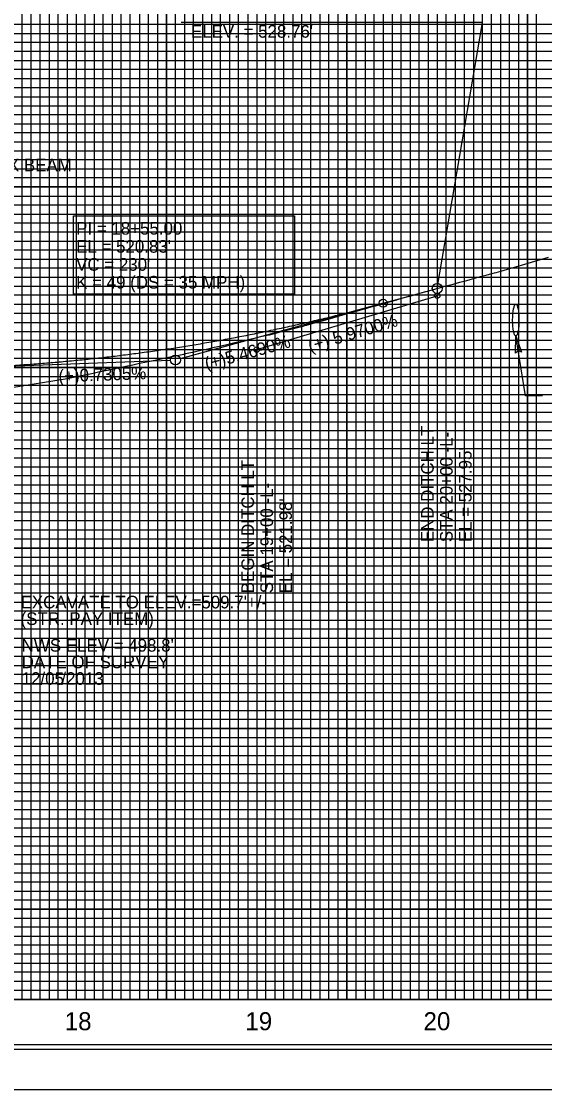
# Model space of a CAD drawing. Extents: x 572694 to 574378, y -52955 to -51855.
# Drawn here: x 573681 to 573971, y -52955 to -52363 of the extents above; entities that cross this region are included whole.
import ezdxf

# ---------------------------------------------------------------- set-up
doc = ezdxf.new("R2010")
doc.units = 0
for name, color, linetype in [('Exist Profile Cell', 7, 'Continuous'), ('Exist Vertical Profile Ground Line', 7, 'Continuous'), ('Exist Vertical Profile Horizontal Axis Label Major', 7, 'Continuous'), ('Prop Drainage Structure Box Reinforced Concrete', 7, 'Continuous'), ('Prop Drainage Structure Box Reinforced Concrete Label', 7, 'Continuous'), ('Prop Grid Mask', 7, 'Continuous'), ('Prop PFL Text', 7, 'Continuous'), ('Prop Vertical Profile Curve Label', 7, 'Continuous'), ('Prop Vertical Profile Ditch Grade Left', 7, 'Continuous'), ('Prop Vertical Profile Ditch Grade Left Label', 7, 'Continuous'), ('Prop Vertical Profile Grade', 7, 'Continuous'), ('Prop Vertical Profile Grade Label', 7, 'Continuous'), ('Prop VPI Ditch Grade Left Label', 7, 'Continuous'), ('Sheet Cutting Line CELL', 7, 'Continuous'), ('Sheet DOT Grid CELL', 7, 'Continuous'), ('Sheet Plot Border Inside CELL', 7, 'Continuous'), ('Sheet Plot Border Outside CELL', 7, 'Continuous'), ('Sheet Profile CELL', 7, 'Continuous'), ('Sheet Profile Grid Major CELL', 7, 'Continuous'), ('Sheet Profile Grid Middle CELL', 7, 'Continuous'), ('Sheet Profile Grid Minor CELL', 7, 'Continuous'), ('Typical Terminator CELL', 7, 'Continuous')]:
    doc.layers.add(name, color=color, linetype=linetype)

msp = doc.modelspace()

# ---------------------------------------------------------------- linework, layer by layer
at = {"layer": 'Exist Profile Cell'}
msp.add_line((572911.5, -52905.14), (574213.46, -52905.14), dxfattribs=at)
at = {"layer": 'Exist Vertical Profile Ground Line'}
for points in [[(573765.48, -52548.86), (573769.25, -52548.07), (573771.11, -52547.68), (573772.24, -52547.44), (573773.03, -52547.27), (573776.8, -52546.44), (573780.58, -52545.61), (573784.35, -52544.78), (573785.38, -52544.56), (573788.13, -52543.92), (573791.9, -52543.06), (573795.68, -52542.19), (573799.45, -52541.32), (573803.23, -52540.46), (573807, -52539.59), (573810.78, -52538.73), (573814.55, -52537.87), (573816.29, -52537.47), (573818.33, -52537.02), (573818.63, -52536.95), (573822.1, -52536.06), (573825.88, -52535.09), (573829.65, -52534.12), (573833.43, -52533.16), (573837.2, -52532.19), (573838.14, -52531.95), (573839, -52531.72), (573840.98, -52531.16), (573841.43, -52531.03), (573844.75, -52530.09), (573848.53, -52529.03), (573852.3, -52527.96), (573856.08, -52526.89), (573859.85, -52525.83), (573863.63, -52524.76), (573867.4, -52523.7), (573871.18, -52522.64), (573874.95, -52521.58), (573878.73, -52520.52), (573882.5, -52519.46), (573886.28, -52518.4), (573889.04, -52517.63), (573889.52, -52517.47), (573890.05, -52517.32), (573893.83, -52516.26), (573897.61, -52515.2), (573901.38, -52514.13), (573901.93, -52513.98), (573905.16, -52513.09), (573908.93, -52512.06), (573912.71, -52511.02), (573916.48, -52509.99), (573920.26, -52508.95), (573924.03, -52507.92), (573927.81, -52506.89), (573931.58, -52505.85), (573935.36, -52504.82), (573939.13, -52503.79), (573943.18, -52502.69), (573944.1, -52502.44), (573946.68, -52501.7), (573950.46, -52500.61), (573954.23, -52499.53), (573958.12, -52498.42), (573961.78, -52497.35), (573965.56, -52496.26), (573967.35, -52495.73), (573969.33, -52495.16), (573973.11, -52494.07)], [(573675.67, -52566.24), (573705.38, -52561.4), (573707.73, -52561.02), (573708.13, -52560.93), (573716.4, -52559.18), (573720.18, -52558.39), (573723.95, -52557.59), (573727.73, -52556.8), (573731.5, -52556), (573735.28, -52555.21), (573735.71, -52555.12), (573739.05, -52554.41), (573742.83, -52553.62), (573746.6, -52552.82), (573750.38, -52552.03), (573754.15, -52551.24), (573757.93, -52550.44), (573761.7, -52549.65), (573765.48, -52548.86)]]:
    msp.add_lwpolyline(points, dxfattribs=at)
at = {"layer": 'Prop Drainage Structure Box Reinforced Concrete'}
msp.add_ellipse((573955, -52528.89), major_axis=(0, 8.75), ratio=0.2, dxfattribs=at)
at = {"layer": 'Prop Drainage Structure Box Reinforced Concrete Label'}
for p, q in [((573960.31, -52570.84), (573955, -52537.64)), ((573969.72, -52570.84), (573960.31, -52570.84))]:
    msp.add_line(p, q, dxfattribs=at)
at = {"layer": 'Prop Grid Mask'}
msp.add_lwpolyline([(573710.05, -52471.19), (573832.47, -52471.19), (573832.47, -52514.49), (573710.05, -52514.49)], close=True, dxfattribs=at)
at = {"layer": 'Prop Vertical Profile Curve Label'}
for p, q in [((573936.61, -52364.06), (573769.66, -52364.06)), ((573911.5, -52511.34), (573936.61, -52364.06)), ((573881.5, -52519.54), (573769.15, -52550.27)), ((573651.5, -52555.19), (573763.75, -52551.09))]:
    msp.add_line(p, q, dxfattribs=at)
for centre, radius in [((573911.5, -52511.34), 2.75), ((573881.5, -52519.54), 2.25), ((573766.5, -52550.99), 2.75)]:
    msp.add_circle(centre, radius, dxfattribs=at)
at = {"layer": 'Prop Vertical Profile Ditch Grade Left'}
msp.add_line((573811.5, -52545.24), (573911.5, -52515.39), dxfattribs=at)
at = {"layer": 'Prop Vertical Profile Grade'}
msp.add_line((573881.5, -52519.54), (573911.5, -52511.34), dxfattribs=at)
msp.add_spline([(573651.5, -52555.19), (573656.1, -52555.01), (573660.7, -52554.81), (573665.3, -52554.59), (573669.9, -52554.34), (573674.5, -52554.08), (573679.1, -52553.79), (573683.7, -52553.48), (573688.3, -52553.15), (573692.9, -52552.8), (573697.5, -52552.42), (573702.1, -52552.02), (573706.7, -52551.61), (573711.3, -52551.16), (573715.9, -52550.7), (573720.5, -52550.22), (573725.1, -52549.71), (573729.7, -52549.18), (573734.3, -52548.64), (573738.9, -52548.06), (573743.5, -52547.47), (573748.1, -52546.86), (573752.7, -52546.22), (573757.3, -52545.56), (573761.9, -52544.88), (573766.5, -52544.18), (573771.1, -52543.45), (573775.7, -52542.71), (573780.3, -52541.94), (573784.9, -52541.15), (573789.5, -52540.34), (573794.1, -52539.51), (573798.7, -52538.65), (573803.3, -52537.78), (573807.9, -52536.88), (573812.5, -52535.96), (573817.1, -52535.02), (573821.7, -52534.05), (573826.3, -52533.07), (573830.9, -52532.06), (573835.5, -52531.03), (573840.1, -52529.98), (573844.7, -52528.91), (573849.3, -52527.81), (573853.9, -52526.7), (573858.5, -52525.56), (573863.1, -52524.4), (573867.7, -52523.22), (573872.3, -52522.02), (573876.9, -52520.79), (573881.5, -52519.54)], degree=3, dxfattribs=at)
at = {"layer": 'Prop VPI Ditch Grade Left Label'}
for p, q in [((573911.5, -52515.39), (573911.5, -52655.14)), ((573911.5, -52515.39), (573911.5, -52653.73)), ((573811.5, -52545.24), (573811.5, -52655.14)), ((573811.5, -52545.24), (573811.5, -52683.58))]:
    msp.add_line(p, q, dxfattribs=at)
for centre in [(573911.5, -52515.39), (573811.5, -52545.24)]:
    msp.add_circle(centre, 1.5, dxfattribs=at)
at = {"layer": 'Sheet Cutting Line CELL'}
msp.add_line((572694.5, -52955.14), (574378.5, -52955.14), dxfattribs=at)
at = {"layer": 'Sheet DOT Grid CELL'}
for p, q in [((573711.5, -51880.14), (573711.5, -52905.14)), ((573761.5, -51880.14), (573761.5, -52905.14)), ((573811.5, -51880.14), (573811.5, -52905.14)), ((573861.5, -51880.14), (573861.5, -52905.14)), ((573911.5, -51880.14), (573911.5, -52905.14)), ((573961.5, -51880.14), (573961.5, -52905.14)), ((572861.5, -52405.14), (574361.5, -52405.14)), ((572861.5, -52455.14), (574361.5, -52455.14)), ((572861.5, -52505.14), (574361.5, -52505.14)), ((572861.5, -52555.14), (574361.5, -52555.14)), ((572861.5, -52605.14), (574361.5, -52605.14)), ((572861.5, -52655.14), (574361.5, -52655.14)), ((572861.5, -52705.14), (574361.5, -52705.14)), ((572861.5, -52755.14), (574361.5, -52755.14)), ((572861.5, -52805.14), (574361.5, -52805.14)), ((572861.5, -52855.14), (574361.5, -52855.14))]:
    msp.add_line(p, q, dxfattribs=at)
at = {"layer": 'Sheet Plot Border Inside CELL'}
msp.add_lwpolyline([(574374, -51877.59), (572707.5, -51877.59), (572707.5, -52932.69), (574374, -52932.69)], close=True, dxfattribs=at)
at = {"layer": 'Sheet Plot Border Outside CELL'}
msp.add_lwpolyline([(574378.5, -51855.14), (572694.5, -51855.14), (572694.5, -52955.14), (574378.5, -52955.14)], close=True, dxfattribs=at)
at = {"layer": 'Sheet Profile CELL'}
msp.add_line((574361.5, -52905.14), (572861.5, -52905.14), dxfattribs=at)
msp.add_lwpolyline([(574361.5, -51880.14), (572861.5, -51880.14), (572861.5, -52930.14), (574361.5, -52930.14)], close=True, dxfattribs=at)
at = {"layer": 'Sheet Profile Grid Major CELL'}
for points in [[(573711.5, -51880.14), (573711.5, -52905.14), (573761.5, -52905.14), (573761.5, -51880.14)], [(573811.5, -51880.14), (573811.5, -52905.14), (573861.5, -52905.14), (573861.5, -51880.14)], [(573911.5, -51880.14), (573911.5, -52905.14), (573961.5, -52905.14), (573961.5, -51880.14)], [(574361.5, -52455.14), (572861.5, -52455.14), (572861.5, -52405.14), (574361.5, -52405.14)], [(574361.5, -52555.14), (572861.5, -52555.14), (572861.5, -52505.14), (574361.5, -52505.14)], [(574361.5, -52655.14), (572861.5, -52655.14), (572861.5, -52605.14), (574361.5, -52605.14)], [(574361.5, -52755.14), (572861.5, -52755.14), (572861.5, -52705.14), (574361.5, -52705.14)], [(574361.5, -52855.14), (572861.5, -52855.14), (572861.5, -52805.14), (574361.5, -52805.14)]]:
    msp.add_lwpolyline(points, dxfattribs=at)
at = {"layer": 'Sheet Profile Grid Middle CELL'}
for points in [[(573686.5, -51880.14), (573686.5, -52905.14), (573736.5, -52905.14), (573736.5, -51880.14)], [(573786.5, -51880.14), (573786.5, -52905.14), (573836.5, -52905.14), (573836.5, -51880.14)], [(573886.5, -51880.14), (573886.5, -52905.14), (573936.5, -52905.14), (573936.5, -51880.14)], [(574361.5, -52380.14), (572861.5, -52380.14), (572861.5, -52430.14), (574361.5, -52430.14)], [(574361.5, -52480.14), (572861.5, -52480.14), (572861.5, -52530.14), (574361.5, -52530.14)], [(574361.5, -52580.14), (572861.5, -52580.14), (572861.5, -52630.14), (574361.5, -52630.14)], [(574361.5, -52680.14), (572861.5, -52680.14), (572861.5, -52730.14), (574361.5, -52730.14)], [(574361.5, -52780.14), (572861.5, -52780.14), (572861.5, -52830.14), (574361.5, -52830.14)], [(574361.5, -52880.14), (572861.5, -52880.14)]]:
    msp.add_lwpolyline(points, dxfattribs=at)
at = {"layer": 'Sheet Profile Grid Minor CELL'}
for points in [[(573681.5, -51880.14), (573681.5, -52905.14), (573691.5, -52905.14), (573691.5, -51880.14)], [(573696.5, -51880.14), (573696.5, -52905.14), (573701.5, -52905.14), (573701.5, -51880.14)], [(573706.5, -51880.14), (573706.5, -52905.14), (573716.5, -52905.14), (573716.5, -51880.14)], [(573721.5, -51880.14), (573721.5, -52905.14), (573726.5, -52905.14), (573726.5, -51880.14)], [(573731.5, -51880.14), (573731.5, -52905.14), (573741.5, -52905.14), (573741.5, -51880.14)], [(573746.5, -51880.14), (573746.5, -52905.14), (573751.5, -52905.14), (573751.5, -51880.14)], [(573756.5, -51880.14), (573756.5, -52905.14), (573766.5, -52905.14), (573766.5, -51880.14)], [(573771.5, -51880.14), (573771.5, -52905.14), (573776.5, -52905.14), (573776.5, -51880.14)], [(573781.5, -51880.14), (573781.5, -52905.14), (573791.5, -52905.14), (573791.5, -51880.14)], [(573796.5, -51880.14), (573796.5, -52905.14), (573801.5, -52905.14), (573801.5, -51880.14)], [(573806.5, -51880.14), (573806.5, -52905.14), (573816.5, -52905.14), (573816.5, -51880.14)], [(573821.5, -51880.14), (573821.5, -52905.14), (573826.5, -52905.14), (573826.5, -51880.14)], [(573831.5, -51880.14), (573831.5, -52905.14), (573841.5, -52905.14), (573841.5, -51880.14)], [(573846.5, -51880.14), (573846.5, -52905.14), (573851.5, -52905.14), (573851.5, -51880.14)], [(573856.5, -51880.14), (573856.5, -52905.14), (573866.5, -52905.14), (573866.5, -51880.14)], [(573871.5, -51880.14), (573871.5, -52905.14), (573876.5, -52905.14), (573876.5, -51880.14)], [(573881.5, -51880.14), (573881.5, -52905.14), (573891.5, -52905.14), (573891.5, -51880.14)], [(573896.5, -51880.14), (573896.5, -52905.14), (573901.5, -52905.14), (573901.5, -51880.14)], [(573906.5, -51880.14), (573906.5, -52905.14), (573916.5, -52905.14), (573916.5, -51880.14)], [(573921.5, -51880.14), (573921.5, -52905.14), (573926.5, -52905.14), (573926.5, -51880.14)], [(573931.5, -51880.14), (573931.5, -52905.14)], [(573931.5, -52905.14), (573941.5, -52905.14), (573941.5, -51880.14), (573946.5, -51880.14), (573946.5, -52905.14), (573951.5, -52905.14), (573951.5, -51880.14), (573956.5, -51880.14), (573956.5, -52905.14), (573966.5, -52905.14), (573966.5, -51880.14), (573971.5, -51880.14)], [(574311.5, -52365.14), (572911.5, -52365.14), (572911.5, -52370.14), (574311.5, -52370.14)], [(574311.5, -52375.14), (572911.5, -52375.14), (572911.5, -52385.14), (574311.5, -52385.14)], [(574311.5, -52390.14), (572911.5, -52390.14), (572911.5, -52395.14), (574311.5, -52395.14)], [(574311.5, -52400.14), (572911.5, -52400.14)], [(572911.5, -52410.14), (574311.5, -52410.14)], [(574311.5, -52415.14), (572911.5, -52415.14), (572911.5, -52420.14), (574311.5, -52420.14)], [(574311.5, -52425.14), (572911.5, -52425.14), (572911.5, -52435.14), (574311.5, -52435.14)], [(574311.5, -52440.14), (572911.5, -52440.14), (572911.5, -52445.14), (574311.5, -52445.14)], [(574311.5, -52450.14), (572911.5, -52450.14), (572911.5, -52460.14), (574311.5, -52460.14)], [(574311.5, -52465.14), (572911.5, -52465.14), (572911.5, -52470.14), (574311.5, -52470.14)], [(574311.5, -52475.14), (572911.5, -52475.14), (572911.5, -52485.14), (574311.5, -52485.14)], [(574311.5, -52490.14), (572911.5, -52490.14), (572911.5, -52495.14), (574311.5, -52495.14)], [(574311.5, -52500.14), (572911.5, -52500.14), (572911.5, -52510.14), (574311.5, -52510.14)], [(574311.5, -52515.14), (572911.5, -52515.14), (572911.5, -52520.14), (574311.5, -52520.14)], [(574311.5, -52525.14), (572911.5, -52525.14), (572911.5, -52535.14), (574311.5, -52535.14)], [(574311.5, -52540.14), (572911.5, -52540.14), (572911.5, -52545.14), (574311.5, -52545.14)], [(574311.5, -52550.14), (572911.5, -52550.14), (572911.5, -52560.14), (574311.5, -52560.14)], [(574311.5, -52565.14), (572911.5, -52565.14), (572911.5, -52570.14), (574311.5, -52570.14)], [(574311.5, -52575.14), (572911.5, -52575.14), (572911.5, -52585.14), (574311.5, -52585.14)], [(574311.5, -52590.14), (572911.5, -52590.14), (572911.5, -52595.14), (574311.5, -52595.14)], [(574311.5, -52600.14), (572911.5, -52600.14), (572911.5, -52610.14), (574311.5, -52610.14)], [(574311.5, -52615.14), (572911.5, -52615.14), (572911.5, -52620.14), (574311.5, -52620.14)], [(574311.5, -52625.14), (572911.5, -52625.14), (572911.5, -52635.14), (574311.5, -52635.14)], [(574311.5, -52640.14), (572911.5, -52640.14), (572911.5, -52645.14), (574311.5, -52645.14)], [(574311.5, -52650.14), (572911.5, -52650.14), (572911.5, -52660.14), (574311.5, -52660.14)], [(574311.5, -52665.14), (572911.5, -52665.14), (572911.5, -52670.14), (574311.5, -52670.14)], [(574311.5, -52675.14), (572911.5, -52675.14), (572911.5, -52685.14), (574311.5, -52685.14)], [(574311.5, -52690.14), (572911.5, -52690.14), (572911.5, -52695.14), (574311.5, -52695.14)], [(574311.5, -52700.14), (572911.5, -52700.14)], [(572911.5, -52710.14), (574311.5, -52710.14)], [(574311.5, -52715.14), (572911.5, -52715.14), (572911.5, -52720.14), (574311.5, -52720.14)], [(574311.5, -52725.14), (572911.5, -52725.14)], [(572911.5, -52735.14), (574311.5, -52735.14)], [(574311.5, -52740.14), (572911.5, -52740.14), (572911.5, -52745.14), (574311.5, -52745.14)], [(574311.5, -52750.14), (572911.5, -52750.14), (572911.5, -52760.14), (574311.5, -52760.14)], [(574311.5, -52765.14), (572911.5, -52765.14), (572911.5, -52770.14), (574311.5, -52770.14)], [(574311.5, -52775.14), (572911.5, -52775.14), (572911.5, -52785.14), (574311.5, -52785.14)], [(574311.5, -52790.14), (572911.5, -52790.14), (572911.5, -52795.14), (574311.5, -52795.14)], [(574311.5, -52800.14), (572911.5, -52800.14), (572911.5, -52810.14), (574311.5, -52810.14)], [(574311.5, -52815.14), (572911.5, -52815.14), (572911.5, -52820.14), (574311.5, -52820.14)], [(574311.5, -52825.14), (572911.5, -52825.14), (572911.5, -52835.14), (574311.5, -52835.14)], [(574311.5, -52840.14), (572911.5, -52840.14), (572911.5, -52845.14), (574311.5, -52845.14)], [(574311.5, -52850.14), (572911.5, -52850.14), (572911.5, -52860.14), (574311.5, -52860.14)], [(574311.5, -52865.14), (572911.5, -52865.14), (572911.5, -52870.14), (574311.5, -52870.14)], [(574311.5, -52875.14), (572911.5, -52875.14), (572911.5, -52885.14), (574311.5, -52885.14)], [(574311.5, -52890.14), (572911.5, -52890.14), (572911.5, -52895.14), (574311.5, -52895.14)], [(574311.5, -52900.14), (572911.5, -52900.14)]]:
    msp.add_lwpolyline(points, dxfattribs=at)
at = {"layer": 'Typical Terminator CELL'}
msp.add_lwpolyline([(573954.88, -52547.15), (573955, -52537.64), (573958.13, -52546.68), (573956.29, -52545.76)], close=True, dxfattribs=at)

# ---------------------------------------------------------------- texts
at = {"layer": 'Exist Vertical Profile Horizontal Axis Label Major'}
for s, p in [('18', (573705.16, -52922.24)), ('19', (573805.2, -52922.24)), ('20', (573903.88, -52922.24))]:
    msp.add_text(s, height=10, dxfattribs=at).set_placement(p)
at = {"layer": 'Prop PFL Text'}
for s, p in [('1 @ 90\', 1 @ 100\'; 39" BOX BEAM', (573564.03, -52446.48)), ("EXCAVATE TO ELEV.=509.7'+/-", (573680.72, -52688.58)), ('(STR. PAY ITEM)', (573680.72, -52697.76)), ("NWS ELEV = 498.8'", (573681.33, -52712.54)), ('DATE OF SURVEY', (573681.33, -52721.72)), ('12/05', (573681.33, -52730.9)), ('/2013', (573703.32, -52730.9))]:
    msp.add_text(s, height=7, dxfattribs=at).set_placement(p)
at = {"layer": 'Prop Vertical Profile Curve Label'}
msp.add_text("ELEV. = 528.76'", height=7, rotation=360, dxfattribs=at).set_placement((573775.09, -52372.45))
for s, p in [('PI = 18+55.00', (573711.5, -52481.54)), ("EL = 520.83'", (573711.5, -52491.54)), ("VC = 230'", (573711.5, -52501.54)), ('K = 49 (DS = 35 MPH)', (573711.5, -52511.42))]:
    msp.add_text(s, height=7, dxfattribs=at).set_placement(p)
at = {"layer": 'Prop Vertical Profile Ditch Grade Left Label'}
msp.add_text('(+) 5.9700%', height=7, rotation=16.62036, dxfattribs=at).set_placement((573841.11, -52546.68))
at = {"layer": 'Prop Vertical Profile Grade Label'}
for s, rotation, p in [('(+)5.4690%', 15.29356, (573783.85, -52556.61)), ('(+)0.7305%', 2.09174, (573701.83, -52563.36))]:
    msp.add_text(s, height=7, rotation=rotation, dxfattribs=at).set_placement(p)
at = {"layer": 'Prop VPI Ditch Grade Left Label'}
for s, p in [('END DITCH LT', (573909.54, -52651.9)), ('STA 20+00 -L-', (573920.04, -52651.9)), ("EL = 527.95'", (573930.54, -52651.9)), ('BEGIN DITCH LT', (573810.04, -52680.17)), ('STA 19+00 -L-', (573820.54, -52680.17)), ("EL = 521.98'", (573831.04, -52680.17))]:
    msp.add_text(s, height=7, rotation=90, dxfattribs=at).set_placement(p)

doc.saveas('drawing.dxf')
